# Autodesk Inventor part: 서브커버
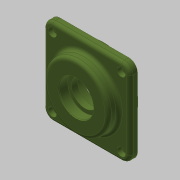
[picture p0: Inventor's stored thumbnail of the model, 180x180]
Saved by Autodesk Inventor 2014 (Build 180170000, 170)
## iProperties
Created: 2018-09
Part Number: 서브커버
Material: 알루미늄 6061
Document SubType Name: Modeling
Designer: mduedu
Density: 2.71 g/cm^3
Appearance: 올리브 녹색
Mass: 206.511 g
Surface Area: 197.007 cm^2
Volume: 76.2032 cm^3
Author: mduedu
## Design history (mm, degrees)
sketch "스케치1"
  geometry: L1 (-40, -40)-(40, -40); L2 (40, -40)-(40, 40); L3 (40, 40)-(-40, 40); L4 (-40, 40)-(-40, -40); L5 (-40, -40)-(40, 40); L6 (40, -40)-(-40, 40); 1 further point
  constraints: 12 end point, 2 midpoint, 2 parallel, 1 horizontal, 1 perpendicular
  dimensions: "d0" = 80 distance of L3.end L2.end; "d1" = 80 distance of L2.end L1.end
extrude "돌출1" new body sketch "스케치1" distance "d2" = 7; taper "d3" = 0 deg
sketch "스케치2"
  geometry: C1 r 30 at (0, 0); 1 further point
  constraints: 1 centre point, 1 coincident
  dimensions: "d4" = 60 diameter of C1
extrude "돌출2" join sketch "스케치2" distance "d5" = 10; taper "d6" = 0 deg
sketch "스케치3"
  geometry: C1 r 32.5 at (0, 0); 1 further point
  constraints: 1 centre point, 1 coincident
  dimensions: "d7" = 65 diameter of C1
extrude "돌출3" join sketch "스케치3" distance "d8" = 9; taper "d9" = 0 deg
sketch "스케치4"
  geometry: L1 (-32.5, -9)-(32.5, -9) reference; L2 (30, 17)-(-30, 17) reference; L3 (0, 17)-(0, -9); L4 (0, -9)-(20, -9); L5 (20, -9)-(20, 3); L6 (20, 3)-(0, 3); L7 (0, 3)-(0, -9); L8 (0, 3)-(12.5, 3); L9 (12.5, 3)-(12.5, 8.7); L10 (12.5, 8.7)-(0, 8.7); L11 (0, 8.7)-(0, 3); L12 (0, 8.7)-(16, 8.7); L13 (16, 8.7)-(16, 17); L14 (16, 17)-(0, 17); L15 (0, 17)-(0, 8.7); 1 further point
  constraints: 26 end point, 6 parallel, 3 horizontal, 3 perpendicular, 2 midpoint, 1 point on line
  dimensions: "d10" = 12 distance of L4.end L5.end; "d12" = 8.3 distance of L12.end L13.end; "d13" = 32 diameter of L13 L3; "d14" = 25 diameter of L9 L3; "d15" = 40 diameter of L5 L3
revolve "회전1" sketch "스케치4" stored, may be unused: angle "d16" = 90 deg
fillet "모깎기1" dims "d17" = 8
fillet "모깎기2" dims "d18" = 3
fillet "모깎기3" dims "d19" = 3
chamfer "모따기1" distance "d20" = 0.8; stored, may be unused: second distance "d21" = 2, angle "d22" = 30 deg
chamfer "모따기2" distance "d23" = 1; stored, may be unused: second distance "d24" = 2, angle "d25" = 30 deg
fillet "모깎기4" dims "d26" = 0.3
sketch "스케치5"
  geometry: A1 r 8 centre (-32, 32) between (-32, 40) and (-40, 32) reference; A2 r 8 centre (-32, -32) between (-40, -32) and (-32, -40) reference; A3 r 8 centre (32, -32) between (32, -40) and (40, -32) reference; A4 r 8 centre (32, 32) between (40, 32) and (32, 40) reference; 5 further points
  constraints: 4 coincident
hole "구멍1" sketch "스케치5" at (-32, 32), (32, 32), (32, -32), (-32, -32) diameter "d27" = 4.5; stored, may be unused: countersink angle "d31" = 90 deg, drill point angle "d33" = 118 deg; dims "d28" = 6, "d29" = 8, "d30" = 4.4, "d32" = 8
node "솔리드1"
